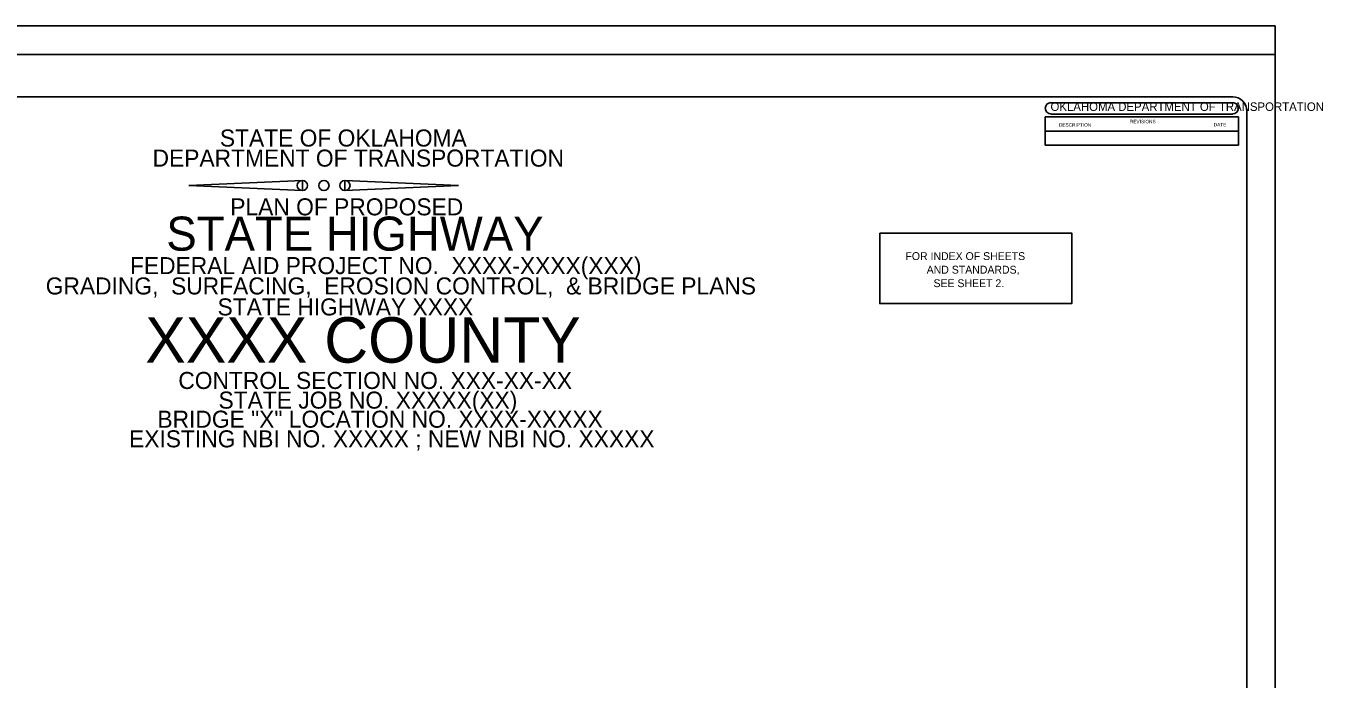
# Model space of a CAD drawing. Extents: x 1458004.1 to 1458040.9, y 194172.7 to 194198.1.
# Drawn here: x 1458018.06 to 1458040.9, y 194184.24 to 194195.74 of the extents above; entities that cross this region are included whole.
import ezdxf

# ---------------------------------------------------------------- set-up
doc = ezdxf.new("R2010")
doc.units = 0
for name, color, linetype in [('Border_0', 7, 'Continuous'), ('Border_9', 7, 'Continuous'), ('IPlot_Plot_Limits', 7, 'Continuous'), ('Text_1', 7, 'Continuous'), ('Text_11', 7, 'Continuous'), ('Text_2', 7, 'Continuous'), ('Text_3', 7, 'Continuous'), ('Text_Box_4', 7, 'Continuous')]:
    doc.layers.add(name, color=color, linetype=linetype)

msp = doc.modelspace()

# ---------------------------------------------------------------- linework, layer by layer
at = {"layer": 'Border_0'}
msp.add_line((1458005.56, 194195.239), (1458040.06, 194195.239), dxfattribs=at)
at = {"layer": 'Border_9'}
for p, q in [((1458007.31, 194194.489), (1458039.31, 194194.489)), ((1458039.56, 194194.239), (1458039.56, 194174.239))]:
    msp.add_line(p, q, dxfattribs=at)
msp.add_arc((1458039.31, 194194.24), 0.25, 0, 90, dxfattribs=at)
at = {"layer": 'IPlot_Plot_Limits'}
for p, q in [((1458004.06, 194195.739), (1458040.06, 194195.739)), ((1458040.06, 194195.739), (1458040.06, 194172.739))]:
    msp.add_line(p, q, dxfattribs=at)
at = {"layer": 'Text_1'}
for points in [[(1458020.929, 194192.928), (1458022.93, 194193.018), (1458022.93, 194192.839)], [(1458025.682, 194192.928), (1458023.68, 194193.018), (1458023.68, 194192.839)]]:
    msp.add_lwpolyline(points, close=True, dxfattribs=at)
for centre in [(1458022.93, 194192.929), (1458023.31, 194192.929), (1458023.68, 194192.929)]:
    msp.add_circle(centre, 0.0896, dxfattribs=at)
at = {"layer": 'Text_Box_4'}
for p, q in [((1458039.31, 194194.388), (1458036.11, 194194.388)), ((1458039.41, 194194.138), (1458036.01, 194194.138)), ((1458036.01, 194194.138), (1458036.01, 194193.638)), ((1458039.31, 194194.188), (1458036.11, 194194.188)), ((1458039.41, 194193.638), (1458039.41, 194194.138)), ((1458039.41, 194193.888), (1458036.01, 194193.888)), ((1458039.41, 194193.638), (1458036.01, 194193.638))]:
    msp.add_line(p, q, dxfattribs=at)
msp.add_lwpolyline([(1458033.096, 194192.092), (1458036.476, 194192.092), (1458036.476, 194190.851), (1458033.096, 194190.851)], close=True, dxfattribs=at)
for centre, start, end in [((1458036.11, 194194.289), 90, 270), ((1458039.31, 194194.289), 270, 90)]:
    msp.add_arc(centre, 0.1, start, end, dxfattribs=at)

# ---------------------------------------------------------------- texts
at = {"layer": 'Text_1'}
msp.add_text('STATE HIGHWAY', height=0.6, dxfattribs=at).set_placement((1458020.535, 194191.782))
at = {"layer": 'Text_11'}
for s, p in [('PLAN OF PROPOSED', (1458021.661, 194192.404)), ('FEDERAL AID PROJECT NO.  XXXX-XXXX(XXX)', (1458019.895, 194191.369)), ('GRADING,  SURFACING,  EROSION CONTROL,  & BRIDGE PLANS', (1458018.412, 194191.011)), ('STATE HIGHWAY XXXX', (1458021.437, 194190.642)), ('CONTROL SECTION NO. XXX-XX-XX', (1458020.746, 194189.347)), ('STATE JOB NO. XXXXX(XX)', (1458021.454, 194189.001)), ('BRIDGE "X" LOCATION NO. XXXX-XXXXX', (1458020.378, 194188.665)), ('EXISTING NBI NO. XXXXX ; NEW NBI NO. XXXXX', (1458019.879, 194188.319))]:
    msp.add_text(s, height=0.3, dxfattribs=at).set_placement(p)
at = {"layer": 'Text_2'}
for s, height, p in [('STATE OF OKLAHOMA', 0.3, (1458021.478, 194193.616)), ('DEPARTMENT OF TRANSPORTATION', 0.3, (1458020.293, 194193.262)), ('XXXX COUNTY', 0.8, (1458020.164, 194189.81))]:
    msp.add_text(s, height=height, dxfattribs=at).set_placement(p)
at = {"layer": 'Text_3'}
for s, height, p in [('OKLAHOMA DEPARTMENT OF TRANSPORTATION', 0.15, (1458036.102, 194194.243)), ('DESCRIPTION', 0.06, (1458036.252, 194193.967)), ('REVISIONS', 0.06, (1458037.501, 194194.026)), ('DATE', 0.06, (1458038.976, 194193.971)), ('FOR INDEX OF SHEETS', 0.13833, (1458033.548, 194191.617)), ('AND STANDARDS,', 0.13833, (1458033.922, 194191.378)), ('SEE SHEET 2.', 0.13833, (1458034.042, 194191.14))]:
    msp.add_text(s, height=height, dxfattribs=at).set_placement(p)

doc.saveas('drawing.dxf')
